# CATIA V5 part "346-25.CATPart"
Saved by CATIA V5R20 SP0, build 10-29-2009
Part number: 346-25
Definition: NONE
Nomenclature: 346-25
Source: Unknown
Description: 346-25
Bounding box of the stored display mesh (mm): x 0 to 63, y -31.5 to 31.5, z -31.5 to 31.5
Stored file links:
  C:\Users\Utente\Desktop\IO LAVORO\3D X SITO CF\X SITO\3D files 346\346-25.CATPart
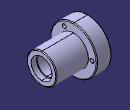
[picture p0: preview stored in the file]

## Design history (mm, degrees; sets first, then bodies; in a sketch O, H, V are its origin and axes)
Body1 "346-25" (main body)
  Solid1: solid without history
